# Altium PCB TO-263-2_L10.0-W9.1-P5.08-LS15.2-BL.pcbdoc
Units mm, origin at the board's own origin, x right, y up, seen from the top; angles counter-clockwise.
Board outline 22.81 x 29.1 mm, 2 copper layers (Top Layer, Bottom Layer), stack 0 mm thick; 1 components, 0 nets, 3 pads, 0 vias.
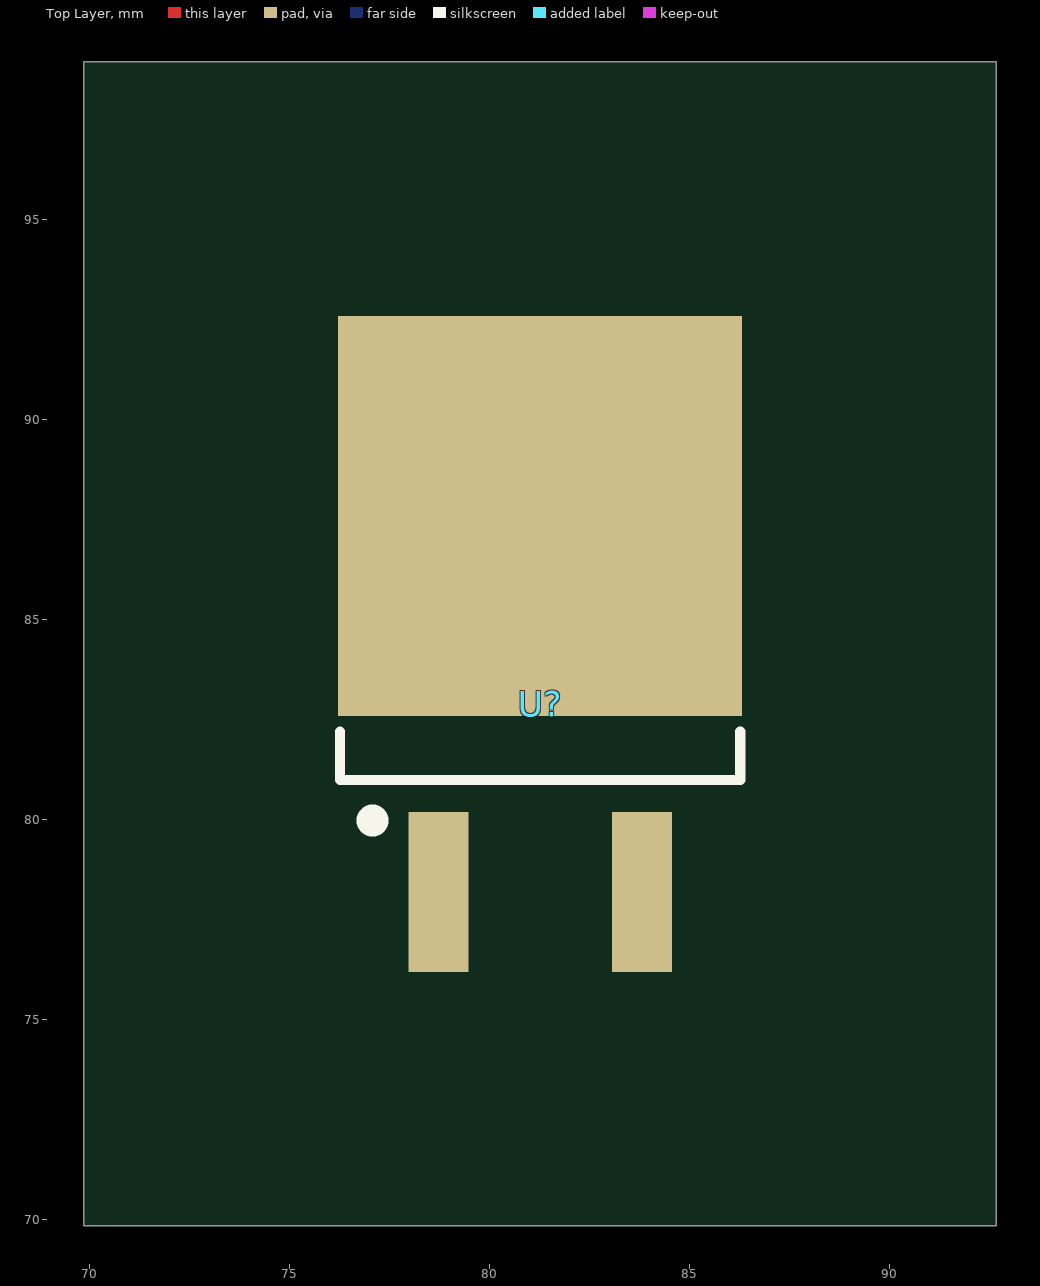
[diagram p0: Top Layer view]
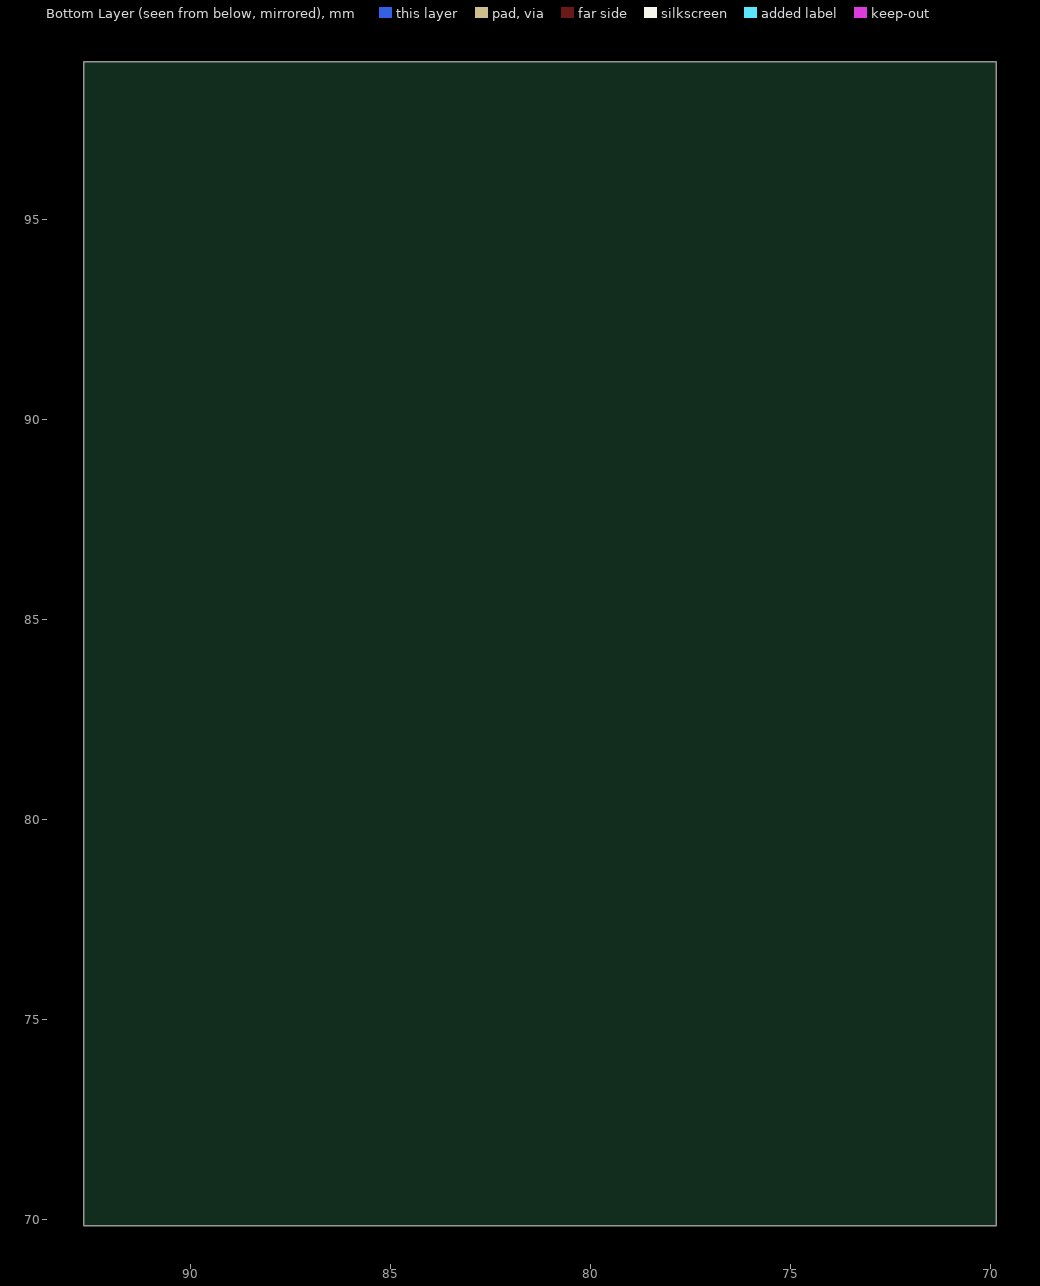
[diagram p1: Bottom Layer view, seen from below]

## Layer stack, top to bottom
Top Layer: signal copper (thickness not stored)
Bottom Layer: signal copper (thickness not stored)

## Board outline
92.66,69.85 69.85,69.85 69.85,98.95 92.66,98.95

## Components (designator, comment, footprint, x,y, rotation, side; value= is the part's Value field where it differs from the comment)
U? "" TO-263-2_L10.0-W9.1-P5.08-LS15.2-BL 81.26,82.9 r0 top

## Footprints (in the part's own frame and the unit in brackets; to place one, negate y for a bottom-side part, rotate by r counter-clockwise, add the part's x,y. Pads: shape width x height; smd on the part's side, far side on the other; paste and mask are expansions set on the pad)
TO-263-2_L10.0-W9.1-P5.08-LS15.2-BL [mm]
  rect 1.5x4 smd: 1(-2.54,-4.7) 3(2.54,-4.7)
  rect 10.1x10 smd: 4(0,4.7)
  silkscreen extent -5,-3.12 5,-0.7

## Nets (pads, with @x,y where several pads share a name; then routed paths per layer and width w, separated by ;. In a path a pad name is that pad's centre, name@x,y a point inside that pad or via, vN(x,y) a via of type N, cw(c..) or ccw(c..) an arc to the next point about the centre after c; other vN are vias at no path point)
pads on no net: U?.1 U?.3 U?.4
